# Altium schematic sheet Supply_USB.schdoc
size 439 x 288 mm
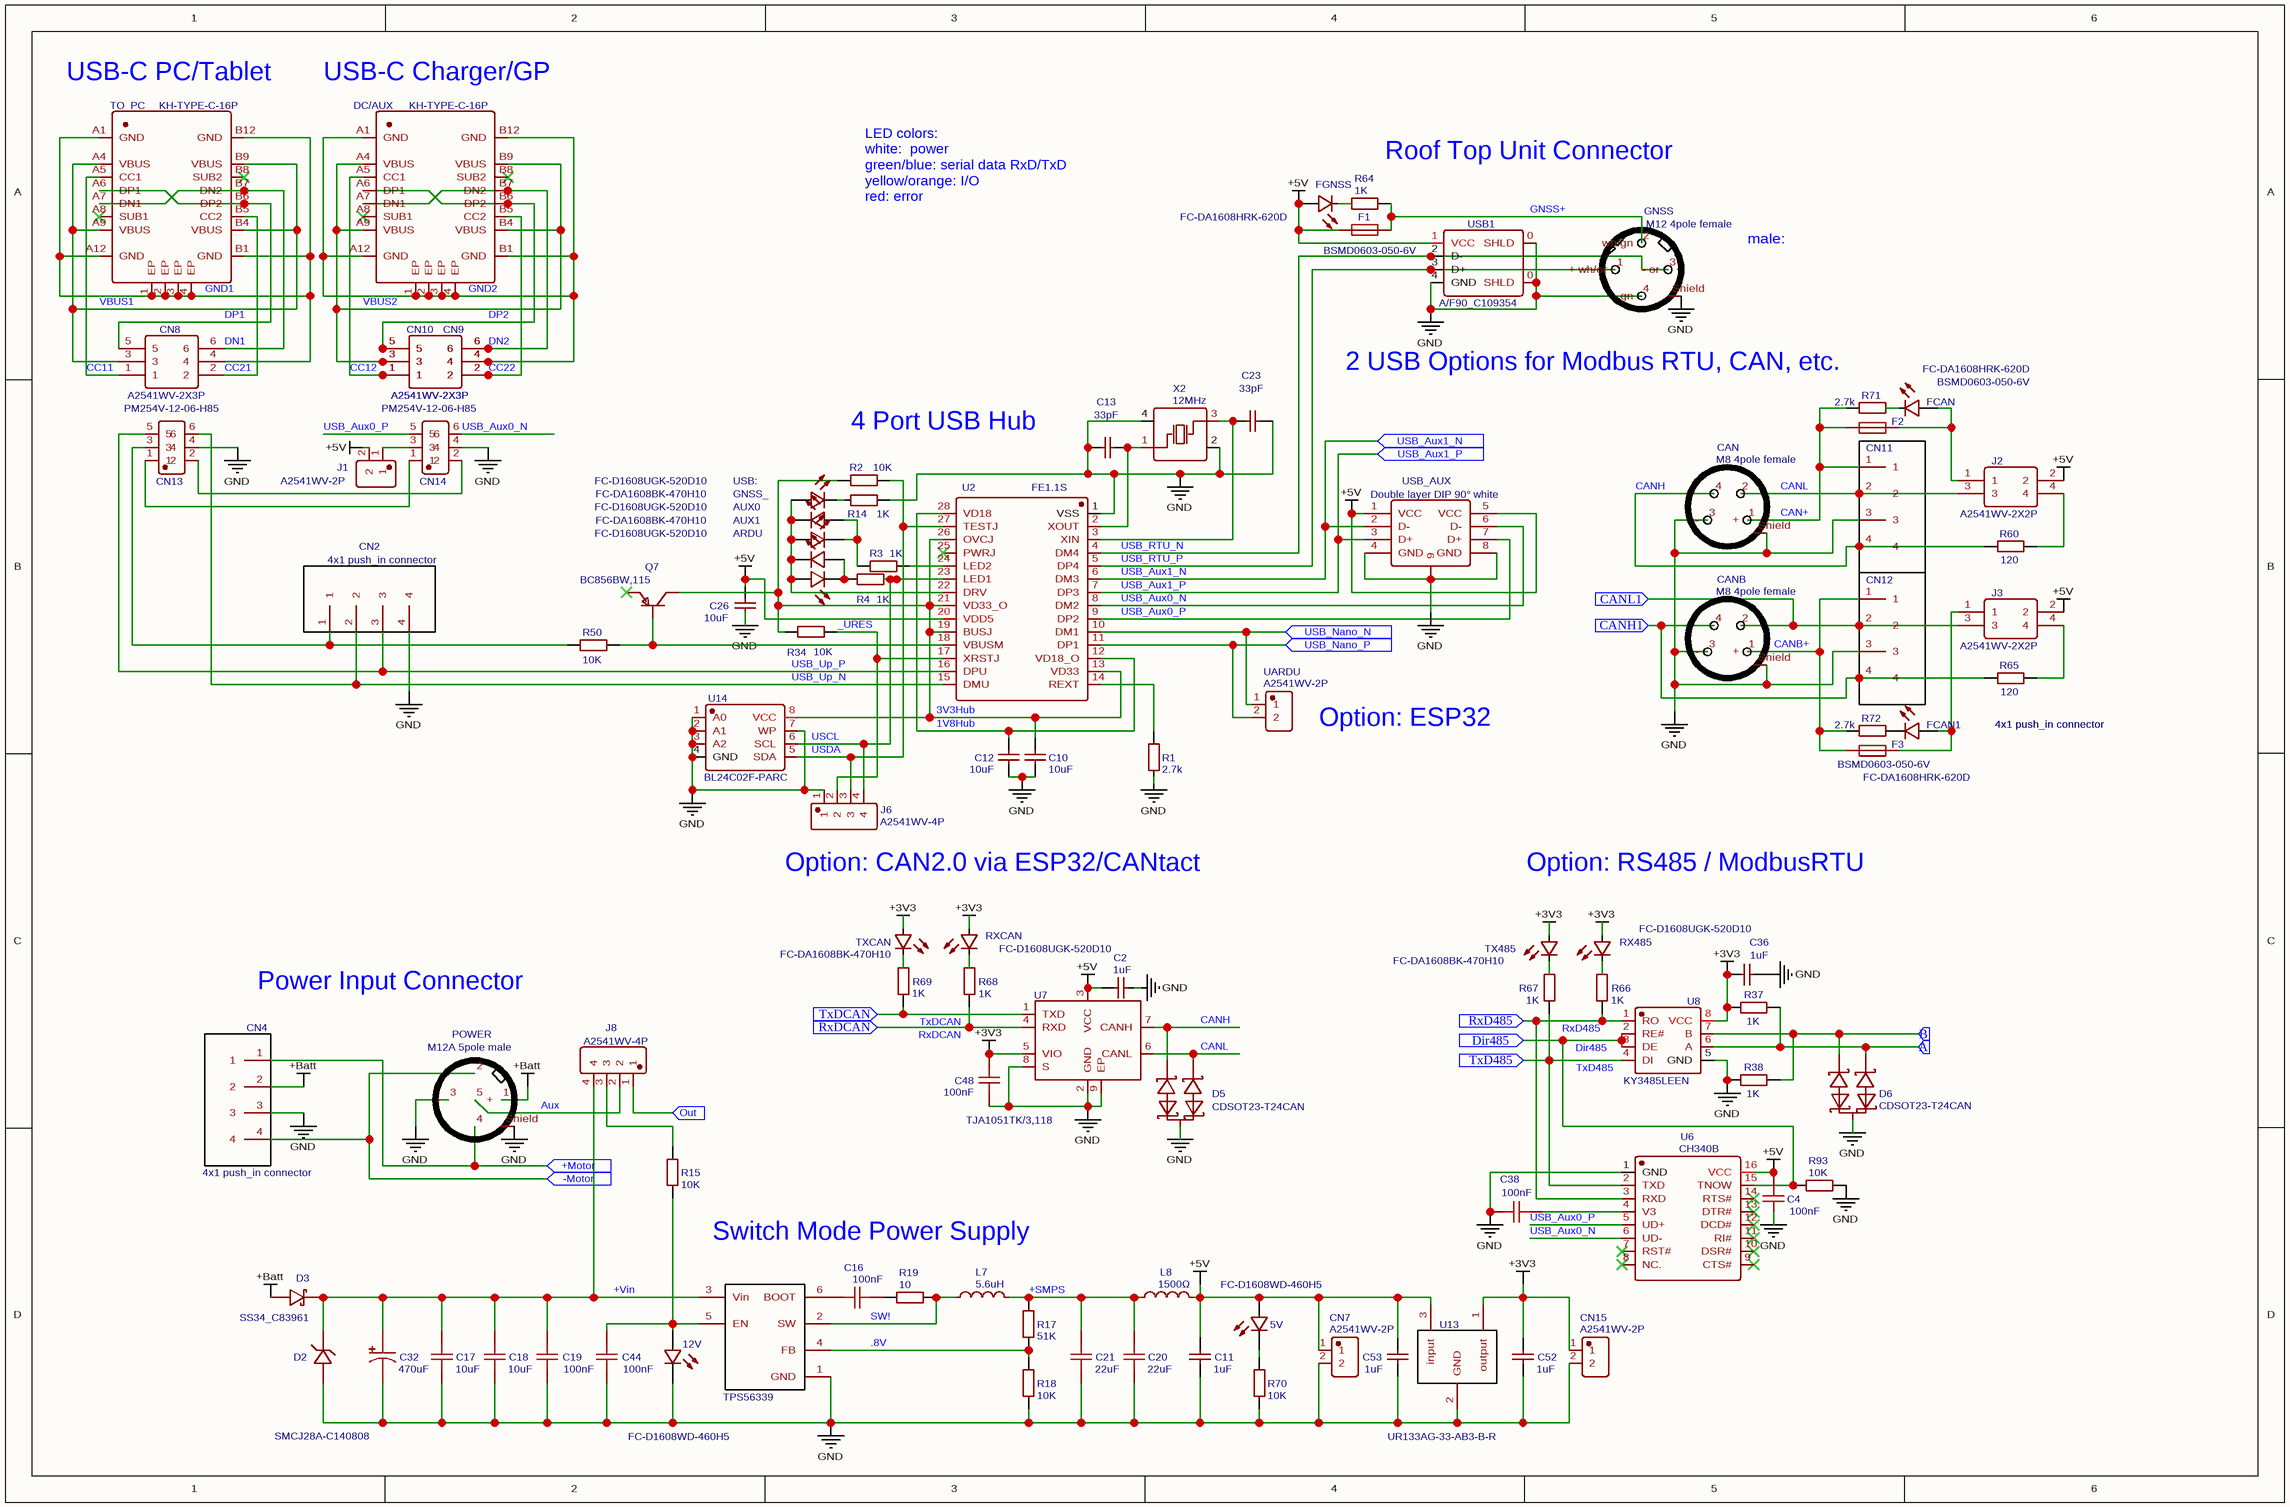
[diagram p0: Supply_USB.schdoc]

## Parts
5V  FC-D1608WD-460H5  [LED0603-RD]
12V  FC-D1608WD-460H5  [LED0603-RD]
ARDU  FC-D1608UGK-520D10  [LED0603-RD]
AUX0  FC-D1608UGK-520D10  [LED0603-RD]
AUX1  FC-DA1608BK-470H10  [LED0603-RD]
C2  1uF  [C0603]
C4  100nF  [C0603]
C10  10uF  [C0805]
C11  1uF  [C0603]
C12  10uF  [C0805]
C13  33pF  [C0603]
C16  100nF  [C0603]
C17  10uF  [C1206]
C18  10uF  [C1206]
C19  100nF  [C0603]
C20  22uF  [C1206]
C21  22uF  [C1206]
C23  33pF  [C0603]
C26  10uF  [C0805]
C32  470uF  [CAP-SMD_BD10.0-L10.3-W10.3-FD]
C36  1uF  [C0603]
C38  100nF  [C0603]
C44  100nF  [C0603]
C48  100nF  [C0603]
C52  1uF  [C0603]
C53  1uF  [C0603]
CAN  M8 4pole female  [M8 FEMALE 4POLE 90°]
CANB  M8 4pole female  [M8 FEMALE 4POLE 90°]
CN2  4x1 push_in connector  [S2C-SMT 3.50/04/180G 3.5SN BK RL]
CN4  4x1 push_in connector  [S2C-SMT 3.50/04/180G 3.5SN BK RL]
CN7  A2541WV-2P  [HDR-TH_P2.54-H-M_A2541WV-2P]
CN8  A2541WV-2X3P  [HDR-TH_6P-P2.54-V-R2-C3-S2.54_A2541WV-2X3P]
CN9  A2541WV-2X3P  [HDR-TH_6P-P2.54-V-R2-C3-S2.54_A2541WV-2X3P]
CN10  A2541WV-2X3P  [HDR-TH_6P-P2.54-V-R2-C3-S2.54_A2541WV-2X3P]
CN11  4x1 push_in connector  [S2C-SMT 3.50/04/180G 3.5SN BK RL]
CN12  4x1 push_in connector  [S2C-SMT 3.50/04/180G 3.5SN BK RL]
CN13  PM254V-12-06-H85  [HDR-TH_6P-P2.54-V-F-R2-C3-S2.54]
CN14  PM254V-12-06-H85  [HDR-TH_6P-P2.54-V-F-R2-C3-S2.54]
CN15  A2541WV-2P  [HDR-TH_P2.54-H-M_A2541WV-2P]
D2  SMCJ28A-C140808  [SMC_L6.9-W5.9-LS7.9-RD]
D3  SS34_C83961  [SMA_L4.4-W2.8-LS5.4-RD]
D5  CDSOT23-T24CAN  [SOT-23_L2.9-W1.3-P0.95-LS2.4-BR]
D6  CDSOT23-T24CAN  [SOT-23_L2.9-W1.3-P0.95-LS2.4-BR]
DC/AUX  KH-TYPE-C-16P  [USB-C-SMD_KH-TYPE-C-16P]
F1  BSMD0603-050-6V  [F0603]
F2  BSMD0603-050-6V  [F0603]
F3  BSMD0603-050-6V  [F0603]
FCAN  FC-DA1608HRK-620D  [LED0603-FD]
FCAN1  FC-DA1608HRK-620D  [LED0603-FD]
FGNSS  FC-DA1608HRK-620D  [LED0603-FD]
GNSS  M12 4pole female  [M12-D FEMALE 4POLE 90°]
GNSS_  FC-DA1608BK-470H10  [LED0603-RD]
J1  A2541WV-2P  [HDR-TH_P2.54-H-M_A2541WV-2P]
J2  A2541WV-2X2P  [HDR-TH_4P-P2.54-V-R2-C2-S2.54_A2541WV-2X2P]
J3  A2541WV-2X2P  [HDR-TH_4P-P2.54-V-R2-C2-S2.54_A2541WV-2X2P]
J6  A2541WV-4P  [HDR-TH_4P-P2.54-V]
J8  A2541WV-4P  [HDR-TH_4P-P2.54-V]
L7  5.6uH  [IND-SMD_L7.3-W6.6_MHCI06030]
L8  1500Ω  [L0603]
POWER  M12A 5pole male  [M12-A MALE 4-5POLE 90°]
Q7  BC856BW,115  [SOT-323-3_L2.2-W1.3-P1.30-LS2.2-BR]
R1  2.7k  [R0603]
R2  10K  [R0603]
R3  1K  [R0603]
R4  1K  [R0603]
R14  1K  [R0603]
R15  10K  [R0603]
R17  51K  [R0603]
R18  10K  [R0603]
R19  10  [R0603]
R34  10K  [R0603]
R37  1K  [R0603]
R38  1K  [R0603]
R50  10K  [R0603]
R60  120  [R1206]
R64  1K  [R0603]
R65  120  [R1206]
R66  1K  [R0603]
R67  1K  [R0603]
R68  1K  [R0603]
R69  1K  [R0603]
R70  10K  [R0603]
R71  2.7k  [R0603]
R72  2.7k  [R0603]
R93  10K  [R0603]
RX485  FC-D1608UGK-520D10  [LED0603-RD]
RXCAN  FC-D1608UGK-520D10  [LED0603-RD]
TO_PC  KH-TYPE-C-16P  [USB-C-SMD_KH-TYPE-C-16P]
TX485  FC-DA1608BK-470H10  [LED0603-RD]
TXCAN  FC-DA1608BK-470H10  [LED0603-RD]
U2  FE1.1S  [SSOP-28_L9.9-W3.9-P0.64-LS6.0-BL]
U4  TPS56339  [SOT-23-6_L2.9-W1.6-P0.95-LS2.8-BL]
U6  CH340B  [SOIC-16_L9.9-W3.9-P1.27-LS6.0-BL]
U7  TJA1051TK/3,118  [HVSON-8_L3.0-W3.0-P0.65-BL-EP]
U8  KY3485LEEN  [SO-8_L4.9-W3.9-P1.27-LS5.9-BL]
U13  UR133AG-33-AB3-B-R  [SOT-89_L4.5-W2.5-P1.50-LS4.2-BR]
U14  BL24C02F-PARC  [SOP-8_L5.0-W4.0-P1.27-LS6.2-BL]
UARDU  A2541WV-2P  [HDR-TH_P2.54-H-M_A2541WV-2P]
USB1  A/F90_C109354  [USB-A-TH_USB-A-F-2]
USB:  FC-D1608UGK-520D10  [LED0603-RD]
USB_AUX  Double layer DIP 90° white  [USB-A-TH_USB-M-51]
X2  12MHz  [OSC-SMD_4P-L3.2-W2.5-BL]

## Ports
+Motor (in), -Motor (in), A (in), B (in), CANH1 (in), CANL1 (in), Dir485 (in), Out (in), RxD485 (in), RxDCAN (in), TxD485 (in), TxDCAN (in), USB_Aux1_N (in), USB_Aux1_P (in), USB_Nano_N (in), USB_Nano_P (in)

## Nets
+3V3: C36.1 C48.2 C52.1 CN15.1 R37.2 RX485.2(A) RXCAN.2(A) TX485.2(+) TXCAN.2(+) U7.5(VIO) U8.8(VCC) U13.1(output)
+5V: 5V.2(+) C2.1 C4.1 C11.1 C26.1 C53.1 CN7.1 F1.2 FGNSS.1(A) J1.2 J2.2 J3.2 L8.2 U2.20(VDD5) U6.16(VCC) U7.3(VCC) U13.3(input) USB1.1(VCC) USB_AUX.1(VCC) USB_AUX.5(VCC)
+Batt: CN4.2 D3.2(A) POWER.1(+)
GND: 12V.1(-) C2.2 C4.2 C10.1 C11.2 C12.1 C13.1 C17.1 C18.1 C19.1 C20.1 C21.1 C23.2 C26.2 C32.2 C36.2 C38.2 C44.1 C48.1 C52.2 C53.2 CAN.3(-) CAN.Shield CANB.3(-) CANB.Shield CN2.4 CN4.3 CN7.2 CN11.3 CN12.3 CN13.4 CN14.4 CN15.2 D2.2(A) D5.3 D6.3 GNSS.4(gn) GNSS.Shield J6.1 POWER.3(-) POWER.Shield R1.1 R14.1 R18.1 R38.2 R70.1 R93.2 U2.1(VSS) U4.1(GND) U6.1(GND) U7.2(GND) U7.8(S) U7.9(EP) U8.5(GND) U13.2(GND) U14.1(A0) U14.2(A1) U14.3(A2) U14.4(GND) U14.7(WP) USB1.0(SHLD) USB1.4(GND) USB_AUX.4(GND) USB_AUX.8(GND) USB_AUX.9 X2.2(GND) X2.4(GND)
1V8Hub: C12.2 U2.12(VD18_O) U2.28(VD18)
3V3Hub: C10.2 Q7.3 R2.2 R34.2 U2.13(VD33) U2.19(BUSJ) U2.21(VD33_O) U2.26(OVCJ) U14.8(VCC)
+Motor: CN4.1 POWER.4 ; port +Motor
+SMPS: C20.2 C21.2 L7.2 L8.1 R17.2
+Vin: C17.2 C18.2 C19.2 C32.1 D2.1(C) D3.1(C) J8.4 U4.3(Vin)
-Motor: CN4.4 POWER.2 ; port -Motor
.8V: R17.1 R18.2 U4.4(FB)
_URES: J6.2 R34.1 U2.17(XRSTJ)
A: D6.1 R37.1 U8.6(A) ; port A
Aux: J8.2 POWER.5
B: D6.2 R38.1 U8.7(B) ; port B
CAN+: CAN.1(+) CN11.1 F2.2 R71.2
CANB+: CANB.1(+) CN12.1 F3.2 R72.2
CANH: CAN.4 CN11.4 D5.2 R60.1 U7.7(CANH)
CANH1: CANB.4 CN12.4 R65.1 ; port CANH1
CANL: CAN.2 CN11.2 D5.1 J2.3 U7.6(CANL)
CANL1: CANB.2 CN12.2 J3.3 ; port CANL1
CC11: CN8.1 TO_PC.A5(CC1)
CC12: CN9.1 CN10.1 DC/AUX.A5(CC1)
CC21: CN8.2 TO_PC.B5(CC2)
CC22: CN9.2 CN10.2 DC/AUX.B5(CC2)
Dir485: R93.1 U6.15(TNOW) U8.2(RE#) U8.3(DE) ; port Dir485
DN1: CN8.6 TO_PC.A7(DN1) TO_PC.B7(DN2)
DN2: CN9.6 CN10.6 DC/AUX.A7(DN1) DC/AUX.B7(DN2)
DP1: CN8.5 TO_PC.A6(DP1) TO_PC.B6(DP2)
DP2: CN9.5 CN10.5 DC/AUX.A6(DP1) DC/AUX.B6(DP2)
GND1: CN8.4 TO_PC.1(EP) TO_PC.2(EP) TO_PC.3(EP) TO_PC.4(EP) TO_PC.A1(GND) TO_PC.A12(GND) TO_PC.B1(GND) TO_PC.B12(GND)
GND2: CN9.4 CN10.4 DC/AUX.1(EP) DC/AUX.2(EP) DC/AUX.3(EP) DC/AUX.4(EP) DC/AUX.A1(GND) DC/AUX.A12(GND) DC/AUX.B1(GND) DC/AUX.B12(GND)
GNSS+: F1.1 GNSS.2(wh/gn) R64.2
Out: J8.1 ; port Out
RxD485: R66.2 U6.3(RXD) U8.1(RO) ; port RxD485
RxDCAN: R68.2 U7.4(RXD) ; port RxDCAN
SW!: L7.1 R19.1 U4.2(SW)
TxD485: R67.2 U6.2(TXD) U8.4(DI) ; port TxD485
TxDCAN: R69.2 U7.1(TXD) ; port TxDCAN
USB_Aux0_N: CN14.6 U2.8(DM2) U6.6(UD-) USB_AUX.6(D-)
USB_Aux0_P: CN14.5 U2.9(DP2) U6.5(UD+) USB_AUX.7(D+)
USB_Aux1_N: U2.6(DM3) USB_AUX.2(D-) ; port USB_Aux1_N
USB_Aux1_P: U2.7(DP3) USB_AUX.3(D+) ; port USB_Aux1_P
USB_Nano_N: U2.10(DM1) UARDU.1 ; port USB_Nano_N
USB_Nano_P: U2.11(DP1) UARDU.2 ; port USB_Nano_P
USB_RTU_N: GNSS.3(-_or) U2.4(DM4) USB1.2(D-)
USB_RTU_P: GNSS.1(+_wh/or) U2.5(DP4) USB1.3(D+)
USB_Up_N: CN2.2 CN13.6 U2.15(DMU)
USB_Up_P: CN2.3 CN13.5 U2.16(DPU)
USCL: J6.4 R4.2 U2.23(LED1) U14.6(SCL)
USDA: J6.3 R2.1 U2.27(TESTJ) U14.5(SDA)
VBUS1: CN8.3 TO_PC.A4(VBUS) TO_PC.A9(VBUS) TO_PC.B4(VBUS) TO_PC.B9(VBUS)
VBUS2: CN9.3 CN10.3 DC/AUX.A4(VBUS) DC/AUX.A9(VBUS) DC/AUX.B4(VBUS) DC/AUX.B9(VBUS)
Net5V_1: 5V.1(-) R70.2
Net12V_2: 12V.2(+) C44.2 R15.1 U4.5(EN)
NetARDU_1: ARDU.1(K) AUX1.2(+) R4.1
NetARDU_2: ARDU.2(A) AUX0.2(A) AUX1.1(-) GNSS_.1(-) U2.22(DRV) USB:.2(A)
NetAUX0_1: AUX0.1(K) GNSS_.2(+) R3.2
NetC13_2: C13.2 U2.2(XOUT) X2.1(OSC1)
NetC16_1: C16.1 U4.6(BOOT)
NetC16_2: C16.2 R19.2
NetC23_1: C23.1 U2.3(XIN) X2.3(OSC2)
NetC38_1: C38.1 U6.4(V3)
NetCN2_1: CN2.1 CN13.3 R50.1
NetCN13_1: CN13.1 CN14.1
NetCN13_2: CN13.2 CN14.2
NetCN14_3: CN14.3 J1.1
NetF2_1: F2.1 FCAN.1(A) J2.1
NetF3_1: F3.1 FCAN1.1(A) J3.1
NetFCAN1_2: FCAN1.2(K) R72.1
NetFCAN_2: FCAN.2(K) R71.1
NetFGNSS_2: FGNSS.2(K) R64.1
NetJ2_4: J2.4 R60.2
NetJ3_4: J3.4 R65.2
NetJ8_3: J8.3 R15.2
NetQ7_1: Q7.1 R50.2 U2.18(VBUSM)
NetR1_2: R1.2 U2.14(REXT)
NetR3_1: R3.1 U2.24(LED2)
NetR14_2: R14.2 USB:.1(K)
NetR66_1: R66.1 RX485.1(K)
NetR67_1: R67.1 TX485.1(-)
NetR68_1: R68.1 RXCAN.1(K)
NetR69_1: R69.1 TXCAN.1(-)

Not connected (* = marked no-connect by the designer): DC/AUX A8(SUB1)* B8(SUB2)*; Q7 2*; TO_PC A8(SUB1)* B8(SUB2)*; U2 25(PWRJ)*; U6 7(RST#)* 8(NC.)* 9(CTS#)* 10(DSR#)* 11(RI#)* 12(DCD#)* 13(DTR#)* 14(RTS#)*

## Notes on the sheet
- (near TO_PC) USB-C PC/Tablet
- (near DC/AUX) USB-C Charger/GP
- LED colors:
  white:  power
  green/blue: serial data RxD/TxD
  yellow/orange: I/O
  red: error
- (near R64) Roof Top Unit Connector
- male:
- (near R71) 2 USB Options for Modbus RTU, CAN, etc.
- 4 Port USB Hub
- Option: ESP32
- Option: CAN2.0 via ESP32/CANtact
- Option: RS485 / ModbusRTU
- Power Input Connector
- Switch Mode Power Supply

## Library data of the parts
5V 12V = FC-D1608WD-460H5: BOM_Manufacturer: NATIONSTAR; SMT Type: Extend
ARDU AUX0 RX485 RXCAN USB: = FC-D1608UGK-520D10: BOM_Manufacturer: NATIONSTAR; SMT Type: Extend
AUX1 GNSS_ TX485 TXCAN = FC-DA1608BK-470H10: BOM_Manufacturer: NATIONSTAR
C2 C11 C36 C52 C53 = 1uF: BOM_Manufacturer Part: CL10A105KP8NNNC; BOM_Manufacturer: SAMSUNG; nameAlias: Capacitance
C4 C16 C19 C38 C44 C48 = 100nF: BOM_Manufacturer: YAGEO; BOM_Manufacturer Part: CC0603JRX7R8BB104; nameAlias: Capacitance; Contributor: LCSC
C10 C12 C26 = 10uF: BOM_Manufacturer: WTC; BOM_Manufacturer Part: 0805X106K100; nameAlias: Capacitance
C13 C23 = 33pF: BOM_Manufacturer: SAMSUNG; BOM_Manufacturer Part: CL10C330JB8NNNC; nameAlias: Capacitance
C17 C18 = 10uF: BOM_Manufacturer: CCTC; BOM_Manufacturer Part: TCC1206X7R106K250HT; nameAlias: Capacitance; Contributor: LCSC
C20 C21 = 22uF: BOM_Manufacturer: SAMSUNG; BOM_Manufacturer Part: CL31B226KPHNNNE; nameAlias: Capacitance
C32 = 470uF: BOM_Manufacturer: CapXon; BOM_Manufacturer Part: HV471M016F105R; nameAlias: Capacitance; Contributor: LCSC
CAN CANB = M8 4pole female: BOM_Manufacturer: Binder, Escha; Contributor: GoRoNb
CN2 CN4 CN11 CN12 = 4x1 push_in connector: BOM_Manufacturer: Weidmuller; BOM_Manufacturer Part: 1825660000; Contributor: Renaud Varin
CN7 CN15 J1 UARDU = A2541WV-2P: BOM_Manufacturer: CJT(Changjiang Connectors); Contributor: LCSC
CN8-CN10 = A2541WV-2X3P: BOM_Manufacturer: Changjiang Connectors; Contributor: LCSC
CN13 CN14 = PM254V-12-06-H85: BOM_Manufacturer: XFCN; Contributor: LCSC
D2 = SMCJ28A-C140808: BOM_Manufacturer: Yenji; Contributor: LCSC
D3 = SS34_C83961: BOM_Manufacturer: STARSEA; BOM_Manufacturer Part: SS34; SMT Type: Extend
D5 D6 = CDSOT23-T24CAN: BOM_Manufacturer: Yenji Elec; Contributor: LCSC; SMT Type: Extend
DC/AUX TO_PC = KH-TYPE-C-16P: BOM_Manufacturer: Shenzhen Kinghelm Elec; Contributor: LCSC
F1-F3 = BSMD0603-050-6V: BOM_Manufacturer: BHFUSE; Contributor: LCSC
FCAN FCAN1 FGNSS = FC-DA1608HRK-620D: BOM_Manufacturer: NATIONSTAR
GNSS = M12 4pole female: BOM_Manufacturer: Binder, Escha; Contributor: GoRoNb
J2 J3 = A2541WV-2X2P: BOM_Manufacturer: Changjiang Connectors; Contributor: LCSC
J6 J8 = A2541WV-4P: BOM_Manufacturer: Changjiang Connectors; Contributor: LCSC
L7 = 5.6uH: BOM_Manufacturer: Chilisin Elec; BOM_Manufacturer Part: MHCI06030-5R6M-R8; nameAlias: Inductance; Contributor: LCSC
L8 = 1500Ω: BOM_Manufacturer: Sunlord; BOM_Manufacturer Part: GZ1608D152CTF; nameAlias: Value
POWER = M12A 5pole male: BOM_Manufacturer: Binder, Escha; Contributor: GoRoNb
Q7 = BC856BW,115: BOM_Manufacturer: Nexperia; SMT Type: Extend
R1 R71 R72 = 2.7k: BOM_Manufacturer: RALEC; BOM_Manufacturer Part: RTT03272JTP; nameAlias: Resistance (Ohms)
R2 R15 R18 R34 R50 R70 R93 = 10K: BOM_Manufacturer: RALEC; BOM_Manufacturer Part: RTT03103JTP; nameAlias: Resistance (Ohms)
R3 R4 R14 R37 R38 R64 R66-R69 = 1K: BOM_Manufacturer: RALEC; BOM_Manufacturer Part: RTT03102JTP; nameAlias: Resistance (Ohms)
R17 = 51K: BOM_Manufacturer: RALEC; BOM_Manufacturer Part: RTT03513JTP; nameAlias: Resistance (Ohms)
R19 = 10: BOM_Manufacturer: RALEC; BOM_Manufacturer Part: RTT03100JTP; nameAlias: Resistance (Ohms)
R60 R65 = 120: BOM_Manufacturer: RALEC; BOM_Manufacturer Part: RTT06121JTP; nameAlias: Resistance (Ohms)
U2 = FE1.1S: BOM_Manufacturer: TERMINUS; SMT Type: Extend
U4 = TPS56339: BOM_Manufacturer: Texas Instruments; BOM_Manufacturer Part: TPS56339DDCR; Contributor: TheLastDroid
U6 = CH340B: BOM_Manufacturer: WCH
U7 = TJA1051TK/3,118: BOM_Manufacturer: NXP
U8 = KY3485LEEN: BOM_Manufacturer: Keysemi; Contributor: LCSC
U13 = UR133AG-33-AB3-B-R: BOM_Manufacturer: UTC; SMT Type: Extend
U14 = BL24C02F-PARC: BOM_Manufacturer: BL; Contributor: LCSC; SMT Type: Extend
USB1 = A/F90_C109354: BOM_Manufacturer: LCSC; Contributor: 立创EDA官方封装库
USB_AUX = Double layer DIP 90° white: BOM_Manufacturer: ValuePro
X2 = 12MHz: BOM_Manufacturer: YXC; BOM_Manufacturer Part: X322512MSB4SI; nameAlias: Frequency; SMT Type: Basic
